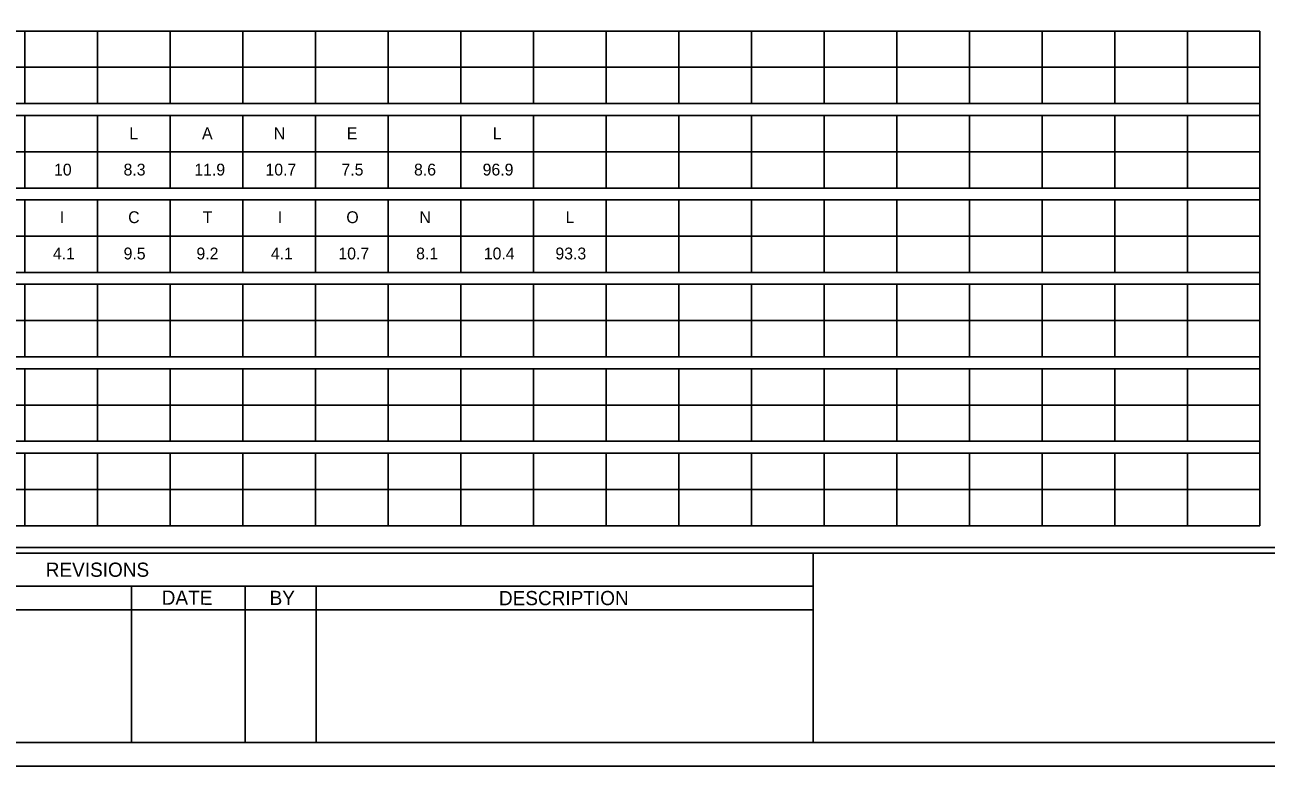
# Model space of a CAD drawing. Extents: x 17890628 to 17890844, y 17897508 to 17897992.
# Drawn here: x 17890726.43 to 17890772.14, y 17897507.74 to 17897535.03 of the extents above; entities that cross this region are included whole.
import ezdxf

# ---------------------------------------------------------------- set-up
doc = ezdxf.new("R2010")
doc.units = 0
for name, color, linetype in [('GSSign', 7, 'Continuous'), ('PlotBorder_dp', 7, 'Continuous'), ('SheetBorder_dp', 7, 'Continuous'), ('SheetLinesMisc2_dp', 7, 'Continuous'), ('TextMisc', 7, 'Continuous')]:
    doc.layers.add(name, color=color, linetype=linetype)

msp = doc.modelspace()

# ---------------------------------------------------------------- linework, layer by layer
at = {"layer": 'PlotBorder_dp'}
msp.add_lwpolyline([(17890700.471, 17897507.741), (17890844.259, 17897507.741), (17890844.259, 17897600.116), (17890700.471, 17897600.116)], close=True, dxfattribs=at)
at = {"layer": 'SheetBorder_dp'}
for p, q in [((17890705.263, 17897515.585), (17890839.466, 17897515.585)), ((17890755.459, 17897515.585), (17890755.459, 17897508.613)), ((17890705.263, 17897514.365), (17890755.459, 17897514.365)), ((17890730.361, 17897514.365), (17890730.361, 17897508.613)), ((17890734.544, 17897514.365), (17890734.544, 17897508.613)), ((17890737.158, 17897514.365), (17890737.158, 17897508.613)), ((17890705.263, 17897513.493), (17890755.459, 17897513.493)), ((17890705.263, 17897508.613), (17890839.466, 17897508.613))]:
    msp.add_line(p, q, dxfattribs=at)
at = {"layer": 'SheetLinesMisc2_dp'}
for p, q in [((17890706.142, 17897534.804), (17890771.912, 17897534.804)), ((17890726.429, 17897534.804), (17890726.429, 17897532.131)), ((17890729.104, 17897534.804), (17890729.104, 17897532.131)), ((17890731.779, 17897534.804), (17890731.779, 17897532.131)), ((17890734.455, 17897534.804), (17890734.455, 17897532.131)), ((17890737.131, 17897534.804), (17890737.131, 17897532.131)), ((17890739.806, 17897534.804), (17890739.806, 17897532.131)), ((17890742.481, 17897534.804), (17890742.481, 17897532.131)), ((17890745.157, 17897534.804), (17890745.157, 17897532.131)), ((17890747.833, 17897534.804), (17890747.833, 17897532.131)), ((17890750.508, 17897534.804), (17890750.508, 17897532.131)), ((17890753.183, 17897534.804), (17890753.183, 17897532.131)), ((17890755.859, 17897534.804), (17890755.859, 17897532.131)), ((17890758.535, 17897534.804), (17890758.535, 17897532.131)), ((17890761.21, 17897534.804), (17890761.21, 17897532.131)), ((17890763.885, 17897534.804), (17890763.885, 17897532.131)), ((17890766.561, 17897534.804), (17890766.561, 17897532.131)), ((17890769.237, 17897534.804), (17890769.237, 17897532.131)), ((17890771.912, 17897516.593), (17890771.912, 17897534.804)), ((17890706.142, 17897533.468), (17890771.912, 17897533.468)), ((17890706.142, 17897532.131), (17890771.912, 17897532.131)), ((17890706.142, 17897531.696), (17890771.912, 17897531.696)), ((17890726.429, 17897531.696), (17890726.429, 17897529.023)), ((17890729.104, 17897531.696), (17890729.104, 17897529.023)), ((17890731.779, 17897531.696), (17890731.779, 17897529.023)), ((17890734.455, 17897531.696), (17890734.455, 17897529.023)), ((17890737.131, 17897531.696), (17890737.131, 17897529.023)), ((17890739.806, 17897531.696), (17890739.806, 17897529.023)), ((17890742.481, 17897531.696), (17890742.481, 17897529.023)), ((17890745.157, 17897531.696), (17890745.157, 17897529.023)), ((17890747.833, 17897531.696), (17890747.833, 17897529.023)), ((17890750.508, 17897531.696), (17890750.508, 17897529.023)), ((17890753.183, 17897531.696), (17890753.183, 17897529.023)), ((17890755.859, 17897531.696), (17890755.859, 17897529.023)), ((17890758.535, 17897531.696), (17890758.535, 17897529.023)), ((17890761.21, 17897531.696), (17890761.21, 17897529.023)), ((17890763.885, 17897531.696), (17890763.885, 17897529.023)), ((17890766.561, 17897531.696), (17890766.561, 17897529.023)), ((17890769.237, 17897531.696), (17890769.237, 17897529.023)), ((17890706.142, 17897530.359), (17890771.912, 17897530.359)), ((17890706.142, 17897529.023), (17890771.912, 17897529.023)), ((17890706.142, 17897528.588), (17890771.912, 17897528.588)), ((17890726.429, 17897528.588), (17890726.429, 17897525.916)), ((17890729.104, 17897528.588), (17890729.104, 17897525.916)), ((17890731.779, 17897528.588), (17890731.779, 17897525.916)), ((17890734.455, 17897528.588), (17890734.455, 17897525.916)), ((17890737.131, 17897528.588), (17890737.131, 17897525.916)), ((17890739.806, 17897528.588), (17890739.806, 17897525.916)), ((17890742.481, 17897528.588), (17890742.481, 17897525.916)), ((17890745.157, 17897528.588), (17890745.157, 17897525.916)), ((17890747.833, 17897528.588), (17890747.833, 17897525.916)), ((17890750.508, 17897528.588), (17890750.508, 17897525.916)), ((17890753.183, 17897528.588), (17890753.183, 17897525.916)), ((17890755.859, 17897528.588), (17890755.859, 17897525.916)), ((17890758.535, 17897528.588), (17890758.535, 17897525.916)), ((17890761.21, 17897528.588), (17890761.21, 17897525.916)), ((17890763.885, 17897528.588), (17890763.885, 17897525.916)), ((17890766.561, 17897528.588), (17890766.561, 17897525.916)), ((17890769.237, 17897528.588), (17890769.237, 17897525.916)), ((17890706.142, 17897527.252), (17890771.912, 17897527.252)), ((17890706.142, 17897525.916), (17890771.912, 17897525.916)), ((17890706.142, 17897525.48), (17890771.912, 17897525.48)), ((17890726.429, 17897525.48), (17890726.429, 17897522.808)), ((17890729.104, 17897525.48), (17890729.104, 17897522.808)), ((17890731.779, 17897525.48), (17890731.779, 17897522.808)), ((17890734.455, 17897525.48), (17890734.455, 17897522.808)), ((17890737.131, 17897525.48), (17890737.131, 17897522.808)), ((17890739.806, 17897525.48), (17890739.806, 17897522.808)), ((17890742.481, 17897525.48), (17890742.481, 17897522.808)), ((17890745.157, 17897525.48), (17890745.157, 17897522.808)), ((17890747.833, 17897525.48), (17890747.833, 17897522.808)), ((17890750.508, 17897525.48), (17890750.508, 17897522.808)), ((17890753.183, 17897525.48), (17890753.183, 17897522.808)), ((17890755.859, 17897525.48), (17890755.859, 17897522.808)), ((17890758.535, 17897525.48), (17890758.535, 17897522.808)), ((17890761.21, 17897525.48), (17890761.21, 17897522.808)), ((17890763.885, 17897525.48), (17890763.885, 17897522.808)), ((17890766.561, 17897525.48), (17890766.561, 17897522.808)), ((17890769.237, 17897525.48), (17890769.237, 17897522.808)), ((17890706.142, 17897524.145), (17890771.912, 17897524.145)), ((17890706.142, 17897522.808), (17890771.912, 17897522.808)), ((17890706.142, 17897522.372), (17890771.912, 17897522.372)), ((17890726.429, 17897522.372), (17890726.429, 17897519.7)), ((17890729.104, 17897522.372), (17890729.104, 17897519.7)), ((17890731.779, 17897522.372), (17890731.779, 17897519.7)), ((17890734.455, 17897522.372), (17890734.455, 17897519.7)), ((17890737.131, 17897522.372), (17890737.131, 17897519.7)), ((17890739.806, 17897522.372), (17890739.806, 17897519.7)), ((17890742.481, 17897522.372), (17890742.481, 17897519.7)), ((17890745.157, 17897522.372), (17890745.157, 17897519.7)), ((17890747.833, 17897522.372), (17890747.833, 17897519.7)), ((17890750.508, 17897522.372), (17890750.508, 17897519.7)), ((17890753.183, 17897522.372), (17890753.183, 17897519.7)), ((17890755.859, 17897522.372), (17890755.859, 17897519.7)), ((17890758.535, 17897522.372), (17890758.535, 17897519.7)), ((17890761.21, 17897522.372), (17890761.21, 17897519.7)), ((17890763.885, 17897522.372), (17890763.885, 17897519.7)), ((17890766.561, 17897522.372), (17890766.561, 17897519.7)), ((17890769.237, 17897522.372), (17890769.237, 17897519.7)), ((17890706.142, 17897521.036), (17890771.912, 17897521.036)), ((17890706.142, 17897519.7), (17890771.912, 17897519.7)), ((17890706.142, 17897519.264), (17890771.912, 17897519.264)), ((17890726.429, 17897519.264), (17890726.429, 17897516.593)), ((17890729.104, 17897519.264), (17890729.104, 17897516.593)), ((17890731.779, 17897519.264), (17890731.779, 17897516.593)), ((17890734.455, 17897519.264), (17890734.455, 17897516.593)), ((17890737.131, 17897519.264), (17890737.131, 17897516.593)), ((17890739.806, 17897519.264), (17890739.806, 17897516.593)), ((17890742.481, 17897519.264), (17890742.481, 17897516.593)), ((17890745.157, 17897519.264), (17890745.157, 17897516.593)), ((17890747.833, 17897519.264), (17890747.833, 17897516.593)), ((17890750.508, 17897519.264), (17890750.508, 17897516.593)), ((17890753.183, 17897519.264), (17890753.183, 17897516.593)), ((17890755.859, 17897519.264), (17890755.859, 17897516.593)), ((17890758.535, 17897519.264), (17890758.535, 17897516.593)), ((17890761.21, 17897519.264), (17890761.21, 17897516.593)), ((17890763.885, 17897519.264), (17890763.885, 17897516.593)), ((17890766.561, 17897519.264), (17890766.561, 17897516.593)), ((17890769.237, 17897519.264), (17890769.237, 17897516.593)), ((17890706.142, 17897517.928), (17890771.912, 17897517.928)), ((17890706.142, 17897516.593), (17890771.912, 17897516.593)), ((17890705.5, 17897515.791), (17890839.233, 17897515.791))]:
    msp.add_line(p, q, dxfattribs=at)

# ---------------------------------------------------------------- texts
at = {"layer": 'GSSign'}
for s, height, p in [('L', 0.436, (17890730.275, 17897530.822)), ('A', 0.436, (17890732.954, 17897530.822)), ('N', 0.436, (17890735.594, 17897530.822)), ('E', 0.436, (17890738.287, 17897530.822)), ('L', 0.436, (17890743.661, 17897530.822)), ('10', 0.4357, (17890727.504, 17897529.485)), ('8.3', 0.4357, (17890730.064, 17897529.485)), ('11.9', 0.4357, (17890732.67, 17897529.485)), ('10.7', 0.4357, (17890735.29, 17897529.485)), ('7.5', 0.4357, (17890738.088, 17897529.485)), ('8.6', 0.4357, (17890740.761, 17897529.485)), ('96.9', 0.4357, (17890743.287, 17897529.485)), ('I', 0.436, (17890727.715, 17897527.732)), ('C', 0.436, (17890730.234, 17897527.732)), ('T', 0.436, (17890732.981, 17897527.732)), ('I', 0.436, (17890735.741, 17897527.732)), ('O', 0.436, (17890738.268, 17897527.732)), ('N', 0.436, (17890740.958, 17897527.732)), ('L', 0.436, (17890746.34, 17897527.732)), ('4.1', 0.4357, (17890727.462, 17897526.396)), ('9.5', 0.4357, (17890730.066, 17897526.396)), ('9.2', 0.4357, (17890732.749, 17897526.396)), ('4.1', 0.4357, (17890735.488, 17897526.396)), ('10.7', 0.4357, (17890737.975, 17897526.396)), ('8.1', 0.4357, (17890740.838, 17897526.396)), ('10.4', 0.4357, (17890743.33, 17897526.396)), ('93.3', 0.4357, (17890745.967, 17897526.396))]:
    msp.add_text(s, height=height, dxfattribs=at).set_placement(p)
at = {"layer": 'TextMisc'}
for s, p in [('REVISIONS', (17890727.199, 17897514.712)), ('BY', (17890735.442, 17897513.675))]:
    msp.add_text(s, height=0.5229, dxfattribs=at).set_placement(p)
for s, height, rotation, p in [('DATE', 0.5229, 359.8693, (17890731.469, 17897513.684)), ('DESCRIPTION', 0.52276, 0.0498, (17890743.887, 17897513.666))]:
    msp.add_text(s, height=height, rotation=rotation, dxfattribs=at).set_placement(p)

doc.saveas('drawing.dxf')
